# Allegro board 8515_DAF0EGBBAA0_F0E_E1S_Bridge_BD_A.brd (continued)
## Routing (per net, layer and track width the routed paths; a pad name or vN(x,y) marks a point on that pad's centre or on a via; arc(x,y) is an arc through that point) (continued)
P3V3_E1S_2: length 47.7
  TOP w0.305: v3(114.3,48.13) 114.3,48.51 114.81,49.02 R746.1
  TOP w0.508: R245.2 89.03,36.8 R246.2 88.4,37.85 v3(88.39,37.85)
  IN1 w0.508: 75.82,37.27 75.82,37.28 75.82,37.98 76.61,38.76 84.53,38.76 85.08,38.21 85.82,38.21 85.83,38.2 88.04,38.2 v3(88.39,37.85)
  VCC w0.508: v3(114.3,48.13) 114.1,48.13 113.62,47.66 113.07,47.66 111.52,46.1 111.51,46.1 110.32,44.91 107.17,44.91 105.55,43.29 94.35,43.29 90.93,39.88 89.52,39.88 88.39,38.75 v3(88.39,37.85)
  vias: v3(69.11,24.94) v3(69.77,24.99) v3(70,24.1) v3(70.64,24.08) v3(75.82,34.21)
P3V3_E1S_2_CB: length 1.7
  TOP w0.109: v3(65.34,19.6) 65.46,19.71 U28.B1
  BOTTOM w0.109: v3(65.34,19.6) 64.96,19.76 R459.1
P3V3_E1S_2_DVDT: length 2.2
  TOP w0.109: C67.1 v3(63.56,27.18) 63.61,27.13 64.93,27.13 U10.1
P3V3_E1S_2_GATE: length 3.3
  TOP w0.109: v3(64.44,22.83) 64.44,22.72 64.55,22.62 U28.A6
  BOTTOM w0.109: C121.1 v1(65.03,21.96) 64.55,21.96 64.44,22.07 v3(64.44,22.83)
P3V3_E1S_2_ILM: length 4.3
  TOP w0.109: v2(70.87,27.69) 70.3,27.69 70,27.38 R198.1 68.57,26.74 U10.7
P3V3_E1S_2_ISENSE: length 3.4
  TOP w0.109: U28.A1 64.12,20.12 v3(63.9,19.89)
  BOTTOM w0.109: v3(63.9,19.89) 63.4,20.39 v1(63.22,20.39) 63.22,19.78 R500.1
P3V3_E1S_2_OV: length 7.9
  TOP w0.203: U28.D3 67.52,21.12 68.24,20.4 v3(68.24,19.8)
  BOTTOM w0.254: R498.2 v1(68.88,22.65) 69.19,22.65 69.44,22.39 69.44,21.22 69.19,20.97 68.62,20.97 68.31,20.66 R499.1 68.24,20.35 v3(68.24,19.8)
P3V3_E1S_2_REG: length 1.4
  TOP w0.109: v3(66.96,19.69) 66.54,20.12 U28.D1
  BOTTOM w0.109: v3(66.96,19.69) 67,19.73 C130.2
P3V3_E1S_2_SCALED: length 10.1
  TOP w0.254: R746.2 R749.1 C284.2 115.84,46.79 117.27,45.36 117.53,45.36 117.79,45.11 v2(117.79,44.45) 118.82,43.41 119.53,43.41 120.53,42.41 121.28,42.1 U35.D1
P3V3_E1S_3: length 59.7
  TOP w0.381: R747.1 117.88,52.11 117.28,52.7 116.77,52.7 116.05,51.98 v3(116.05,51.13) ; R260.2 R261.2
  TOP w0.508: v3(110.74,36.3) 111.08,35.96 R260.2
  VCC w0.508: v3(97.94,33.3) 99.19,34.54 100.01,34.54 101.35,35.88 101.35,37.19 102.74,38.58 v3(102.92,38.58) 103.4,38.1 104.14,38.1 105.66,36.58 110.46,36.58 v3(110.74,36.3) ; v3(96.11,44.35) 96.47,44.7 97.69,44.7 98.32,44.07 105.18,44.07 106.84,45.73 108.75,45.73 109.88,46.86 111.2,46.86 112.83,48.49 113.23,48.49 114.71,49.96 114.88,49.96 v3(116.05,51.13)
  BOTTOM w0.508: v3(102.92,38.58) 102.69,38.81 100.69,38.81 98.67,36.79 98.03,36.79 95.83,38.99 95.83,42.52 96.11,42.8 v3(96.11,44.35)
  vias: v2(100.77,35.5)
P3V3_E1S_3_CB: length 2.5
  TOP w0.109: U29.B1 92.46,25.68 v3(92.35,25.58) 92.3,25.58 92.05,25.32 92,25.32 91.17,24.49 R461.1
P3V3_E1S_3_DVDT: length 3.1
  TOP w0.109: U9.1 92.4,34.38 91.97,34.8 v2(91.57,34.8) 90.57,34.8 C66.1
P3V3_E1S_3_GATE: length 3.1
  TOP w0.109: U29.A6 91.55,28.76 91.44,28.87 v3(91.44,28.98)
  BOTTOM w0.109: v3(91.44,28.98) 90.96,28.98 90.87,29.07 v1(90.87,29.57) 91.77,29.57 C124.1
P3V3_E1S_3_ILM: length 3.3
  TOP w0.109: U9.7 95.1,33.14 95.39,33.43 R197.1 96.6,33.64 v2(97.14,34.17)
P3V3_E1S_3_ISENSE: length 3.3
  TOP w0.109: U29.A1 91.57,25.87 v3(91.57,25.63) 91.52,25.58 90.45,25.58 90.19,25.32 R503.1
P3V3_E1S_3_OV: length 6.8
  TOP w0.203: 94.18,26.92 93.84,27.26 U29.D3
  TOP w0.254: 94.18,26.92 94.79,26.92 95.83,25.89 R502.1 96.69,25.89 96.99,25.59 v3(96.99,25.27) 96.99,24.09 96.67,23.77 96.11,23.77 R501.2
P3V3_E1S_3_REG: length 2.3
  TOP w0.109: C131.2 93.75,25.22 v3(94.11,25.58) 93.7,25.98 93.7,26.02 U29.D1
P3V3_E1S_3_SCALED: length 13.3
  TOP w0.127: U35.D2 121.82,42.5 121.18,42.5 120.81,42.87
  TOP w0.254: R747.2 R750.1 C285.2 117.07,50.02 116.46,49.4 116.46,46.89 117.48,45.87 117.86,45.87 119.01,44.71 v3(119.01,44.42) 119.48,43.95 119.73,43.95 120.81,42.87
P3V3_EDGE: length 50.4
  TOP w0.305: R462.1 133.32,17.91 v3(133.78,17.45)
  TOP w0.381: v3(119.28,20.85) R307.2 ; GF1.B11 25.85,3.43 ; 88.88,3.91 GF2.B11
  TOP w0.457: R23.1 v3(16.81,13.61) ; R24.1 v3(19.56,13.61)
  TOP w0.508: 25.85,3.43 25.85,8.69 v3(25.15,9.4)
  IN1 w0.508: v3(123.81,15.64) 123.96,15.49 130.42,15.49 131.39,15.9 131.61,16.12 131.61,16.94 132.12,17.45 v3(133.78,17.45)
  IN2 w0.508: v3(25.15,9.4) 24.46,10.08 24.46,14.35 22.1,16.71 16.56,16.71 16.05,16.2 16.05,14.58 16.81,13.82 v3(16.81,13.61)
  BOTTOM w0.508: R22.1 25.55,11.23 v3(25.22,11.56) ; v3(25.78,9.78) 25.4,9.4 v3(25.15,9.4) 23.77,10.78 R21.1 ; v3(19.56,13.61) 19.56,13.38 17.83,11.65 R7.1 16.81,12.11 v3(16.81,13.61)
  vias: v2(102.9,11.46) v2(105.18,14.4) v2(123.47,16.33) v3(28.37,12.12) v3(28.96,11.68) v3(56.52,13.21) v3(56.82,13.77) v3(57.15,13.13) v3(105.08,16.38) v3(105.09,15.72) v3(105.89,16.36) v3(105.89,15.7) v3(121.92,15.85) v3(122.61,16.46) v3(122.61,15.82) v3(124.47,16.28) v3(126.09,18.66)
P3V3_EDGE_CB: length 3.2
  TOP w0.254: R463.1 131,15.88 v3(130.59,16.29) 130.31,16.57 130.31,16.95 129.98,17.28 U30.B1
P3V3_EDGE_E1S_EN: length 3.9
  TOP w0.254: R308.1 120.24,15.64 120.68,16.08 U18.2
  TOP w0.508: v2(119.79,13.92) 120.28,14.41 ; 120.28,14.41 R305.2 ; 120.28,14.41 120.23,14.46 120.23,14.55 120.21,14.56 120.21,15.17 R308.1
P3V3_EDGE_GATE: length 2
  TOP w0.254: v3(126.83,16.25) 127.19,16.61 U30.A6
  BOTTOM w0.254: v3(126.83,16.25) 127.13,16.55 C127.1
P3V3_EDGE_ISENSE: length 3.6
  TOP w0.109: U30.A1 129.69,16.14 v3(130.9,14.94) 130.98,14.86 R475.1
P3V3_EDGE_OCP_DVDT: length 1.3
  TOP w0.109: C87.2 v3(119.55,16.57) 120.14,16.57 U18.1
P3V3_EDGE_OCP_FLT_N: length 11.4
  TOP w0.109: R309.1 121.77,20.86 120.8,20.86 R307.1 120.8,19.84 v5(121,19.64) 121.18,19.45 U18.6 ; v3(126.16,17.91) 126.29,17.78 U30.C7
  BOTTOM w0.109: v5(121,19.64) 122.39,18.24 122.39,17.3 122.71,16.98 124.35,16.98 125.27,17.91 v3(126.16,17.91)
P3V3_EDGE_OCP_ILM: length 2.1
  TOP w0.254: R306.1 v3(119.7,18.96) 119.82,19.08 120.43,19.08 120.68,18.82 U18.7
P3V3_EDGE_OV: length 8
  TOP w0.254: U30.D3 128.69,18.85 129.58,19.74 129.58,20.79 v2(129.79,21) 130.06,20.73 130.06,19.86 130.25,19.66 v3(131.33,19.66) 131.84,19.66 R474.1 132.11,19.78 132.91,18.98 R473.2
P3V3_EDGE_REG: length 3.2
  TOP w0.305: U30.D1 130.69,18.28 v3(130.96,18) 131.35,17.62 131.35,17.24 131.7,16.89 C132.2
P3V3_EDGE_UV: length 4.6
  TOP w0.109: U30.D2 129.19,18.63 129.51,18.94 v3(129.99,18.94) 130.38,18.94 130.62,19.18 131.85,19.18 R473.1 R462.2
P12V_AUX: length 7.6
  TOP w0.254: R450.1 88.87,56.11 v3(88.47,56.52) ; R173.1 37.87,57.08 v3(37.47,57.48) ; v3(13.21,57.48) 13.21,57.79 13.26,57.84 R439.1 ; v3(62.99,56.36) 63.39,55.96 R178.1
  TOP w0.305: v3(120.47,48.66) 120.27,48.66 R765.1
  TOP w0.508: R524.1 14.99,35.97 R525.1 14.98,35.26 14.55,34.83
  BOTTOM w0.356: R296.1 145.61,18.07 145.64,18.05 v3(145.64,17.98)
  BOTTOM w0.381: v3(145.11,29.77) 145.56,29.32 R297.1
  vias: v1(12.95,52.88) v1(19.89,45.75) v1(20.07,39.88) v1(38.14,53.26) v3(6.76,34.6) v3(6.77,33.79) v3(6.77,33.03) v3(6.77,32.27) v3(7.52,34.6) v3(7.53,33.79) v3(7.53,33.03) v3(7.53,32.27) v3(11.63,34.87) v3(11.63,34.11) v3(11.63,33.35) v3(12.4,34.87) v3(12.4,34.11) v3(12.4,33.35) v3(13.56,33.18) v3(13.56,32.54) v3(13.56,31.91) v3(13.56,31.27) v3(13.56,30.61) v3(13.57,29.95) v3(14.32,33.18) v3(14.32,32.54) v3(14.32,31.91) v3(14.32,31.27) v3(14.32,30.61) v3(14.33,29.95) v3(20.02,62.27) v3(20.46,61.32) v3(20.84,62.3) v3(21.3,61.33) v3(21.42,61.97) v3(28.42,48.82) v3(32.49,48.79) v3(33.15,48.79) v3(33.78,48.79) v3(34.42,48.79) v3(44.87,62.27) v3(45.5,61.29) v3(46.13,62.27) v3(46.8,61.43) v3(47.05,60.19) v3(58.22,48.64) v3(58.88,48.64) v3(59.51,48.64) v3(70.44,62.08) v3(71.06,61.1) v3(71.54,62.07) v3(72.28,61.43) v3(72.56,60.67) v3(84.15,48.82) v3(95.77,62.28) v3(96.45,61.24) v3(97.08,62.29) v3(97.7,61.66) v3(98.02,60.6)
P12V_AUX_0_ISENSE: length 1.3
  TOP w0.109: v3(11.88,28.71) 11.83,28.66 U33.A1
  BOTTOM w0.109: R511.1 12.44,28.99 12.16,28.71 v3(11.88,28.71)
P12V_AUX_CB: length 1.5
  TOP w0.109: v3(11.9,29.34) 11.72,29.16 U33.B1
  BOTTOM w0.109: R510.1 11.71,29.34 v3(11.9,29.34)
P12V_AUX_EN_MP5022: length 35.8
  TOP w0.109: R531.2 6.37,25.02 v3(6.58,25.02) ; U34.1 18.69,29.96 18.87,29.79 21.21,29.79 21.49,30.07 v3(21.89,30.07) 20.78,28.96 R522.2 21.6,27.64 R523.2
  IN2 w0.124: v3(21.89,30.07) 21.89,31.93 20.36,33.45 19.04,33.45 17.99,34.49 15.37,34.49 14.11,35.75 13.02,36.2 11.29,36.2 10.93,36.06 9.79,34.91 9.79,31.3 9.34,30.86 9.34,28.9 7.83,27.38 7.83,25.58 7.27,25.02 v3(6.58,25.02)
P12V_AUX_FB_MP5022: length 7.9
  TOP w0.109: R525.2 15.5,36.76 15.7,36.55 17.58,36.55 17.81,36.78 v3(18.27,36.78) 18.7,36.78 R526.2 17.57,35.25 17.26,35.25 16.79,34.77 16.41,34.77 16.3,34.66 U34.11
P12V_AUX_GATE: length 2
  TOP w0.109: U33.A6 8.83,27.71 v3(8.64,27.52) 8.69,27.47 C171.1
P12V_AUX_HSC_PWRGD: length 24
  TOP w0.109: v3(7.66,30.11) 8.28,30.11 U33.D7 ; U34.10 17.3,34.65 17.41,34.76 17.85,34.76 v3(18.71,35.62)
  IN1 w0.124: v3(7.66,30.11) 7.66,30.46 10.16,32.96 10.16,35.31 11.13,36.27 18.06,36.27 v3(18.71,35.62)
  BOTTOM w0.109: v3(7.66,30.11) v1(6.9,30.11) 6.14,29.35 6.14,28.23 5.66,27.75 R514.1 5.66,26.52 R513.2
P12V_AUX_IMON_MP5022: length 3.5
  TOP w0.109: U34.8 18.55,33.46 18.98,33.9 18.98,34.23 v3(19.32,34.56) R520.1 C178.2
P12V_AUX_ISET_MP5022: length 1.9
  TOP w0.109: U34.5 19.93,31.96 R521.1
P12V_AUX_OV: length 5.7
  TOP w0.109: U33.D3 v3(10.33,30.69)
  BOTTOM w0.109: R508.2 9.28,30.42 9.55,30.68 10.33,30.68 v3(10.33,30.69) 9.73,31.3 v1(8.3,31.3) 8.31,31.29 R509.1
P12V_AUX_PD_MP5022: length 2.7
  TOP w0.254: R524.2 16.75,35.74 16.49,35.49 16.49,35.49 15.98,35.27 v3(15.7,35) 15.4,34.69 U34.12
P12V_AUX_REG: length 3.8
  TOP w0.109: U33.D1 11.47,30.16 11.61,30.3 v3(11.61,30.66)
  BOTTOM w0.109: v3(11.61,30.66) 11.61,30.93 11.27,31.27 10.54,31.27 10.43,31.38 v1(10.43,31.73) C170.2
P12V_AUX_SS_MP5022: length 2.2
  TOP w0.109: U34.6 18.94,32.46 v3(19.08,32.61) 19.76,32.61 20.04,32.88 C177.1
P12V_AUX_TIMER_MP5022: length 2
  TOP w0.109: U34.4 19.32,31.46 v3(19.42,31.36) 19.78,31.36 C179.2
P12V_AUX_UV: length 13.8
  TOP w0.109: v3(10.97,30.67) 10.97,30.42 10.83,30.29 U33.D2 ; v3(6.48,24) 2.92,24 R530.2
  BOTTOM w0.109: v3(6.48,24) v1(8,25.53) 8,28 9.2,29.21 R508.1 10.08,30.01 R507.2 10.56,30.01 10.97,30.42 v3(10.97,30.67)
P12V_BIC_SCALED: length 6.4
  TOP w0.127: 120.59,44.63 120.59,44.33 121.22,43.7 U35.B1
  TOP w0.254: R765.2 R768.1 C291.2 119.11,46.4 120.38,45.12 120.59,44.63
P12V_E1S_0: length 9.1
  TOP w0.254: C73.1 17.13,50.44 16.92,50.65 16.91,50.65 16.77,50.8 U11.11
  TOP w0.381: C73.1 17.53,50.92 v3(17.43,51.02)
  IN1 w0.508: v3(17.43,51.02) 17.17,51.28 17.17,53.92 18.39,55.14 v3(20.62,55.14)
  vias: v2(19.25,54.35) v3(20.62,55.78)
P12V_E1S_0_CB: length 3.9
  TOP w0.254: R438.1 14.09,60.91 v3(15.03,59.97) 16,58.99 16,58.8 16.59,58.21 U22.B1
P12V_E1S_0_DVDT: length 1.9
  TOP w0.109: U3.1 24.04,59.69 24.03,59.7 v3(24.03,59.73)
  BOTTOM w0.109: C48.1 23.93,60.2 24.03,60.09 v3(24.03,59.73)
P12V_E1S_0_GATE: length 3.3
  TOP w0.254: v3(19.35,59.41) 19.21,59.27 U22.A6
  BOTTOM w0.109: C109.1 21.12,59.74 19.69,59.74 v3(19.35,59.41)
P12V_E1S_0_ILM: length 2.2
  TOP w0.109: v3(24,56.39) 23.54,56.85 U3.7
  BOTTOM w0.109: R169.2 v3(24,56.39)
P12V_E1S_0_IN_N: length 6.3
  TOP w0.109: v2(18.75,50.52) 17.79,51.48 17.12,51.48 16.93,51.3 U11.12
  TOP w0.254: R227.2 18.45,52.04 17.7,52.04 C74.2 17.41,52.04 16.64,52.04 16.21,51.61 U11.12
P12V_E1S_0_IN_P: length 3.7
  TOP w0.254: U11.13 15.88,52.02 16.41,52.55 17.41,52.55 C74.1 17.7,52.55 18.52,52.55 18.7,52.73 R226.2
P12V_E1S_0_IN_SENN: length 4.7
  TOP w0.254: R220.1B 23.1,52.72 22.84,52.98 21.77,52.98 20.79,52 19.82,52 R227.1
P12V_E1S_0_IN_SENP: length 4.7
  TOP w0.254: R220.2B 23.1,53.74 22.84,53.49 21.54,53.49 20.58,52.52 20.24,52.52 20.03,52.73 R226.1
P12V_E1S_0_ISENSE: length 4.7
  TOP w0.109: R464.1 14.04,61.61 15.08,60.57 15.72,60.57 v3(16.32,59.97) 16.71,59.58 U22.A1
P12V_E1S_0_L: length 120.9
  TOP w0.381: R752.1 v3(116.46,36.05)
  VCC w0.508: v3(36.6,36.58) 36.76,36.58 37.47,37.29 38.63,37.77 47.93,37.77 49.48,36.22 53.21,36.22 53.72,35.71 53.72,29.08 54.64,28.17 56.79,28.17 60.22,24.74 60.22,23.72 61.87,22.07 75.72,22.07 76.56,22.91 82.6,22.91 87.99,28.3 93.01,28.3 93.93,29.21 99.95,29.21 105.64,23.52 109.07,23.52 113.16,27.61 113.16,34.29 114.6,35.73 115.36,36.05 v3(116.46,36.05)
  BOTTOM w0.508: v3(24.89,41.53) 24.89,40.12 25.4,39.62 29.55,39.62 31.41,37.75 35.41,37.75 36.57,36.58 v3(36.6,36.58)
  vias: v2(21.84,45.21) v2(23.55,42.93)
P12V_E1S_0_OV: length 5.9
  TOP w0.254: U22.D3 17.71,56.7 16.97,55.96 v3(15.53,55.96) 15.18,55.96 R441.1 14.29,58.08 R440.2
P12V_E1S_0_REG: length 4.6
  TOP w0.305: U22.D1 16.64,57.14 15.8,57.14 15.37,57.57 v3(15.37,58.14) 15.37,58.8 14.27,59.89 C96.2
P12V_E1S_0_SCALED: length 5.2
  TOP w0.254: R752.2 R754.1 C287.2 119.25,37.72 119.51,37.97 121.29,37.97 U35.J1
P12V_E1S_1: length 7.9
  TOP w0.254: U12.11 43.17,49.04 43.52,48.69 C76.1
  TOP w0.508: v3(44.28,48.69) C76.1
  IN1 w0.508: v3(44.81,54.31) 44.28,53.78 v3(44.28,48.69)
  vias: v2(43.9,53.92) v3(44.81,54.94)
P12V_E1S_1_CB: length 3.6
  TOP w0.254: U23.B1 41.1,57.7 v3(39.93,58.87) 38.91,59.89 R444.1
P12V_E1S_1_DVDT: length 2.2
  TOP w0.109: v3(49.03,59.25) 48.81,59.02 U4.1
  BOTTOM w0.109: C49.1 48.92,59.77 49.03,59.65 v3(49.03,59.25)
P12V_E1S_1_GATE: length 2.5
  TOP w0.254: U23.A6 43.98,58.46 44.26,58.74 v3(44.26,59.14)
  BOTTOM w0.254: C110.1 43.59,58.48 v3(44.26,59.14)
P12V_E1S_1_ILM: length 2.2
  TOP w0.109: v3(48.67,55.7) 48.31,56.06 U4.7
  BOTTOM w0.109: R172.2 49.02,55.35 v3(48.67,55.7)
P12V_E1S_1_IN_N: length 7.2
  TOP w0.109: U12.12 43.28,49.54 43.38,49.45 44.24,49.45 44.92,48.77 v2(44.92,47.34)
  TOP w0.254: R242.2 44.43,50.01 43.81,50.01 C77.2 43.52,50.01 42.6,50.01 42.34,49.76 U12.12
P12V_E1S_1_IN_P: length 7.5
  TOP w0.109: U12.13 41.62,50.92 41.79,51.09 43.57,51.09 44.48,51.99 v2(44.63,51.99)
  TOP w0.254: U12.13 42.11,50.27 42.37,50.52 43.52,50.52 C77.1 43.81,50.52 44.41,50.52 R241.2
P12V_E1S_1_IN_SENN: length 4.7
  TOP w0.254: R235.1B 47.78,52.1 47.52,52.35 46.61,52.35 46,51.74 46,50.27 R242.1
P12V_E1S_1_IN_SENP: length 4.7
  TOP w0.254: R235.2B 47.78,53.11 47.52,52.86 46.38,52.86 45.49,51.96 R241.1
P12V_E1S_1_ISENSE: length 4.6
  TOP w0.109: R465.1 38.8,60.63 39.5,59.93 40.82,59.93 v3(41.01,59.74) 41.09,59.66 41.09,58.59 U23.A1
P12V_E1S_1_L: length 90.6
  IN1 w0.508: v3(61.72,29.84) 61.85,29.97 61.85,36.8 61.29,37.36 60.61,37.36 58.22,39.76 56,39.76 55.12,40.64 52.58,40.64 v3(51.44,41.78)
  VCC w0.508: v3(115.14,38.73) 115.14,38.28 114.63,37.77 114.12,37.77 112.37,36.02 112.37,28.25 111.4,27.28 108.74,27.28 108.08,27.94 105.79,27.94 104.44,26.58 103.72,26.58 99.44,30.86 89.47,30.86 86.23,27.62 83.13,27.62 82.68,28.07 80.14,28.07 79.5,27.43 67.77,27.43 66.8,26.46 63.27,26.46 62.76,26.97 62.76,29.16 62.2,29.72 61.85,29.72 v3(61.72,29.84)
  BOTTOM w0.381: R755.1 115.14,38.2 v3(115.14,38.73)
  vias: v2(46.96,48.97) v2(50.01,43.87)
P12V_E1S_1_OV: length 5.8
  TOP w0.254: U23.D3 42.48,56.17 41.43,55.12 40.01,55.12 v3(39.67,55.45) 39.06,56.06 R445.1 39.06,57.06 R443.2
P12V_E1S_1_REG: length 4.8
  TOP w0.305: U23.D1 41.48,56.56 41.17,56.25 40.44,56.25 40.13,56.56 v3(40.13,57.61) 40.13,57.82 39.07,58.88 C102.2
P12V_E1S_1_SCALED: length 10.3
  TOP w0.254: U35.K3 v4(122.62,36.9)
  IN1 w0.254: v4(122.62,36.9) 122.61,36.9 121.64,37.87 120.55,37.87 120.27,37.59 v3(116.43,37.59)
  BOTTOM w0.254: C288.2 R756.1 R755.2 116.19,38.1 116.43,37.86 v3(116.43,37.59)
P12V_E1S_2: length 2.1
  TOP w0.254: C79.1 69.26,31.77 U13.11
  TOP w0.381: C79.1 69.63,31.72 v3(69.93,31.41)
  vias: v3(67.12,53.94) v3(68.06,53.92) v3(69.65,54.91) v3(69.55,34.69) v3(69.68,54.26) v3(69.7,53.59) v3(70.19,34.8) v3(70.85,34.76) v3(71.44,35.06) v3(71.88,53.47)
P12V_E1S_2_CB: length 3.3
  TOP w0.254: U24.B1 66.71,57.35 v3(65.77,58.29) 65.29,58.78 R448.1
P12V_E1S_2_DVDT: length 2.3
  TOP w0.109: v3(74.53,59.04) 74.33,58.84 U5.1
  BOTTOM w0.109: C54.1 74.6,60.28 74.6,59.11 v3(74.53,59.04)
P12V_E1S_2_GATE: length 3
  TOP w0.254: U24.A6 69.5,58.11 69.64,58.25 v3(69.64,58.78)
  BOTTOM w0.109: v3(69.64,58.78) 69.64,57.67 C111.1
P12V_E1S_2_ILM: length 2.1
  TOP w0.109: R177.2 74.45,55.58 v3(74.47,55.58) 73.83,56.22 U5.7
P12V_E1S_2_IN_N: length 6.1
  TOP w0.109: v2(70.69,31.62) 70.04,32.27 U13.12
  TOP w0.254: R257.2 70.05,33.33 69.4,33.33 C80.2 69.15,33.32 68.72,33.32 68,32.59 U13.12
P12V_E1S_2_IN_P: length 5.6
  TOP w0.109: v2(66.19,34.37) 66.66,34.17 67.27,33.56 U13.13
  TOP w0.254: U13.13 67.67,33 68.5,33.83 69.09,33.83 C80.1 69.43,33.84 69.99,33.84 R256.2
P12V_E1S_2_IN_SENN: length 2.7
  TOP w0.254: R250.1B 72.9,33.72 72.63,33.99 71.98,33.99 R257.1
P12V_E1S_2_IN_SENP: length 2.8
  TOP w0.254: R256.1 71.4,34.14 71.76,34.49 72.64,34.49 72.9,34.75 R250.2B
P12V_E1S_2_ISENSE: length 4.4
  TOP w0.109: U24.A1 66.85,58 66.85,59.54 66.6,59.79 v3(64.94,59.79) R466.1
P12V_E1S_2_L: length 54.4
  TOP w0.381: v3(116.71,43.18) 116.46,42.93 R759.1
  IN1 w0.508: v3(74.01,34.05) 74.83,34.86 74.83,38.26 76.09,39.52 79.53,39.52 81.15,41.15 82.68,41.15 84,39.83 88.23,39.83 90.11,41.71 95.22,41.71 v3(96.52,40.41)
  VCC w0.508: v3(96.52,40.41) 97.69,40.41 98.25,40.97 104.08,40.97 104.65,40.4 110.32,40.4 111.33,39.4 114.05,39.4 116.28,41.63 116.28,42.75 v3(116.71,43.18)
  IN2 w0.508: v3(77.47,42.67) 76.72,42.67 76.67,42.72 v3(76.58,42.72)
  vias: v3(71.47,32.49) v3(71.47,31.86) v3(72.05,31.55) v3(76.99,43.31) v3(77.72,43.31)
P12V_E1S_2_OV: length 5.7
  TOP w0.254: R449.1 64.59,55.94 R447.2 64.71,55.96 v3(65.58,55.09) 66.29,55.09 66.4,54.99 67.2,54.99 68,55.79 U24.D3
P12V_E1S_2_REG: length 3.8
  TOP w0.305: C105.2 65.2,57.76 65.58,57.38 v3(65.58,56.85) 65.58,56.62 65.92,56.28 66.93,56.28 U24.D1
P12V_E1S_2_SCALED: length 12.8
  TOP w0.254: U35.K4 v4(123.42,36.9) ; R759.2 116.53,41.54 R760.1 116.53,40.06 v3(116.48,40.01) C290.2 116.48,39.22 115.99,38.74 v3(115.8,38.74)
  IN1 w0.178: v4(123.42,36.9) 123.01,37.3 123.01,37.9 122.81,38.1 122.17,38.1 121.89,38.38
  IN1 w0.254: v3(115.8,38.74) 116.4,38.14 120.08,38.14 120.32,38.38 121.89,38.38
P12V_E1S_3: length 6.6
  TOP w0.254: C82.1 96.81,39.54 96.55,39.8 96.31,39.9 U14.11
  TOP w0.508: v3(97.62,39.54) C82.1
  BOTTOM w0.508: v3(97.32,43.95) 97.32,39.84 v3(97.62,39.54)
  vias: v3(93.9,54.08) v3(96.44,55.06) v3(96.45,54.39)
P12V_E1S_3_CB: length 3.6
  TOP w0.254: U25.B1 92.19,57.5 91.4,58.29 v3(91.4,58.93) R452.1
P12V_E1S_3_DVDT: length 2
  TOP w0.109: U6.1 99.81,58.78 v3(100.03,59.3)
  BOTTOM w0.109: v3(100.03,59.3) C55.1
P12V_E1S_3_GATE: length 2.4
  TOP w0.254: U25.A6 94.98,58.26 95.19,58.47 v3(95.19,58.85)
  BOTTOM w0.254: v3(95.19,58.85) 95.19,58.59 94.57,57.97 C112.1
P12V_E1S_3_ILM: length 1.2
  TOP w0.109: R180.2 99.31,55.4 99.31,55.4 v3(99.31,55.97) U6.7
P12V_E1S_3_IN_N: length 2.8
  TOP w0.254: R272.2 97.82,40.93 C83.2 96.95,40.95 95.86,40.95 95.68,40.77 U14.12
P12V_E1S_3_IN_P: length 5.7
  TOP w0.109: v2(94.89,43.1) 94.41,42.62 94.41,42.06 94.96,41.52 U14.13
  TOP w0.254: R271.2 97.01,41.76 C83.1 96.95,41.7 96.47,41.7 96.42,41.76 95.94,41.76 95.3,41.12 U14.13
P12V_E1S_3_IN_SENN: length 4.1
  TOP w0.254: R265.1B 100.61,43.46 100.36,43.21 100.36,42.27 98.88,40.79 R272.1
P12V_E1S_3_IN_SENP: length 3
  TOP w0.254: R265.2B 99.59,43.46 99.85,43.21 99.85,42.52 99.09,41.76 R271.1
P12V_E1S_3_ISENSE: length 4.4
  TOP w0.109: R467.1 v3(90.46,59.94) 92.08,59.94 92.33,59.69 92.33,58.15 U25.A1
P12V_E1S_3_L: length 17
  TOP w0.381: v3(114.43,38.55) 114.88,38.1 R757.1
  VCC w0.508: v3(114.43,38.55) 111.72,38.55 111.16,38 105.38,38 103.23,40.16 v3(99.34,40.16)
  vias: v2(101.42,41.43)
P12V_E1S_3_OV: length 5.7
  TOP w0.254: R453.1 90.06,56.1 R451.2 90.19,56.11 v3(91.06,55.24) 91.77,55.24 91.88,55.14 92.68,55.14 93.48,55.94 U25.D3
P12V_E1S_3_REG: length 3.8
  TOP w0.305: C108.2 v3(90.39,57.91) 90.68,57.91 91.06,57.53 91.06,56.77 91.4,56.43 92.41,56.43 U25.D1
P12V_E1S_3_SCALED: length 9.2
  TOP w0.254: U35.K2 v4(121.82,36.9) ; 115.84,36.19 R758.1 R757.2 ; 115.84,36.19 v3(116.46,36.8) ; 115.84,36.19 C289.2
  IN1 w0.254: v3(116.46,36.8) 116.74,37.08 120.52,37.08 120.8,37.36 121.35,37.36 v4(121.82,36.9)
P12V_EDGE: length 172
  TOP w0.381: v3(118.49,49.4) 118.26,49.4 R766.1 ; GF2.B4 84.68,3.46 ; GF2.B6 85.88,3.73 ; 20.57,3.81 20.23,3.81 19.85,3.43 GF1.B1 ; GF1.B5 22.25,3.65 ; GF1.B3 21.05,3.53 ; GF2.B3 84.08,3.48 ; 83.29,3.66 82.88,3.25 GF2.B1 ; GF1.B6 22.85,3.56 ; GF1.B4 21.65,3.62 ; 20.45,3.42 GF1.B2 ; GF2.B2 83.48,3.54 ; GF2.B5 85.28,3.49
  IN1 w0.381: v3(122.65,58.17) 121.67,58.17 120.34,56.84 119.66,56.56 119.19,56.08 118.65,54.8 118.65,52.37 117.35,51.07 117.35,50.04 117.98,49.4 v3(118.49,49.4)
  IN2 w0.305: v3(86.36,7.11) 97.41,7.11 99.09,8.8 131.59,8.8 134.21,11.42 134.21,13.17 135.74,16.85 135.74,19.08 136.08,19.42 136.68,19.42 137.02,19.08 138.15,19.08 138.48,19.22 139.1,19.84 140.15,19.84 142.97,22.65 142.97,27.34 143.62,27.99 144.54,27.99 145.68,29.13 145.68,32.59 144.28,33.99 144.28,38.3 143.98,38.6 141.69,38.6 139.2,41.09 139.2,41.82 138.73,42.3 138.73,45.7 139.57,46.55 139.57,52.82 143.04,56.29 143.04,61.98 142.55,62.46 140.68,62.46 140.07,61.85 122.86,61.85 121.79,60.78 121.79,59.03 v3(122.65,58.17)
  BOTTOM w0.508: R507.1 10.47,28.99 v3(10.47,27.89)
  vias: v1(9.75,25.08) v1(10.93,22.38) v3(9.71,27.89) v3(9.71,27.13) v3(9.71,26.37) v3(10.47,27.13) v3(10.47,26.37) v3(16.46,28.15) v3(16.46,27.51) v3(16.58,20.16) v3(16.58,19.52) v3(17.1,28.15) v3(17.1,27.51) v3(17.22,20.16) v3(17.22,19.52) v3(17.66,15.21) v3(17.86,20.16) v3(17.86,19.52) v3(18.3,15.21) v3(18.49,20.16) v3(18.49,19.52) v3(18.93,15.21) v3(19.57,15.21) v3(20.32,7.11) v3(20.32,6.22) v3(20.32,5.33) v3(20.32,4.45) v3(21.72,7.11) v3(21.72,6.22) v3(21.72,5.33) v3(21.72,4.45) v3(23.24,7.24) v3(23.24,6.35) v3(23.24,5.46) v3(23.24,4.57) v3(83.31,6.99) v3(83.31,6.1) v3(83.34,5.21) v3(83.34,4.32) v3(84.84,6.99) v3(84.84,6.1) v3(84.84,5.21) v3(84.84,4.32) v3(86.23,6.22) v3(86.23,5.33) v3(86.31,4.27) v6(16.44,33.11) v6(16.44,32.21) v6(16.44,31.31) v6(16.44,30.41) v6(17.16,33.11) v6(17.16,32.21) v6(17.16,31.31) v6(17.16,30.41)
P12V_EDGE_BIC_SCALED: length 8.1
  TOP w0.127: U35.C1 121.42,43.03 120.44,44
  TOP w0.254: 120.44,44 118.03,46.41 117.67,46.41 117.07,47.01 C292.2 R769.1 R766.2
P12V_EDGE_R: length 2.9
  TOP w0.254: U33.A2 10.83,28.55 v3(11.21,28.18)
  BOTTOM w0.508: v3(11.21,28.18) 11.28,28.11 11.28,27.66 C180.1 11.68,27.21 11.68,26.12 R538.2
PVCC_1V2_PLL: length 4.7
  TOP w0.254: U35.G3 v4(122.62,39.3)
  BOTTOM w0.305: C228.1 122.11,39.6 121.52,39.6 C229.1 121.29,39.57 120.65,39.57 C230.1
  BOTTOM w0.381: L5.1 119.79,39.7 C230.1 ; C228.1 v4(122.62,39.3) U35.G3
  vias: v1(121.32,38.65)
PVCC_BIC_SPI: length 1.7
  TOP w0.109: U35.B8 v4(126.62,44.1)
  BOTTOM w0.254: v4(126.62,44.1) 126.98,44.47 C300.1
  BOTTOM w0.381: v4(126.62,44.1) 126.99,43.72 C232.1
  vias: v3(127.84,52.47) v3(128.56,52.47)
ADCVREFEXT0: length 0.6
  TOP w0.109: U35.F2 v4(121.82,40.1)
ADCVREFEXT1: length 0.6
  TOP w0.109: U35.G1 v4(121.02,40.1)
BIC_ADCAV33: length 2.8
  TOP w0.109: v4(124.22,36.9) U35.K5
  TOP w0.305: U35.J5 v4(124.22,37.7)
  BOTTOM w0.305: v4(124.22,37.7) C240.1 124.22,36.92 v4(124.22,36.9) C239.1
  vias: v1(118.98,36.62)
BIC_ADCVREFN0: length 3.4
  TOP w0.127: 119.76,41.53 120.5,41.53 121.05,41.3 U35.E1
  TOP w0.254: C204.1 118.75,42.04 118.75,42.04 119.23,42.04 C203.2 119.27,42.02 119.76,41.53
BIC_ADCVREFN1: length 5.6
  TOP w0.254: v4(122.61,38.5) 122.62,38.5 U35.H3
  BOTTOM w0.254: v4(122.61,38.5) 121.96,37.84 121.04,37.84 120.62,38.26 119.96,38.26 119.34,38.88 C206.2 119.23,38.86 C207.1
BIC_ADCVREFP0: length 4.6
  TOP w0.127: 120.17,42.03 120.97,41.7 v4(121.82,41.7) U35.E2
  TOP w0.254: C202.1 118.51,42.8 118.74,42.8 118.75,42.79 119.23,42.79 C203.1 119.39,42.82 120.17,42.03
BIC_ADCVREFP1: length 5.4
  TOP w0.254: U35.J3 v4(122.62,37.7)
  BOTTOM w0.254: C205.1 118.49,38.08 C206.1 119.69,37.65 v1(120.41,37.65) 120.57,37.49 122.11,37.49 122.29,37.67 122.59,37.67 v4(122.62,37.7)
BIC_ESPI_SELECT: length 11.7
  TOP w0.109: U35.D14 v4(132.22,42.5)
  BOTTOM w0.109: v4(132.22,42.5) 132.42,42.5 132.86,42.94 133.3,42.94 133.8,42.44 134.32,42.44 135.25,43.38 135.25,45.14 v1(135.64,45.52) R775.1 135.22,46.97 135.1,47.09 135.1,49.53 135.21,49.64 R779.2
BIC_EXTRST_N: length 220.1
  TOP w0.109: R4594.2 130.46,11.67 133.36,14.57 134.44,17.18 134.44,19.87 133.66,20.65 133.66,22.63 132.86,23.43 132.86,25.04 134.34,26.53 v3(134.34,27.48) ; v3(13.03,13.61) 13.03,13.1 R5.1 ; R619.2 v4(122.17,46.35) 121.74,45.92 121.74,45.57 122.62,44.69 122.62,44.1 U35.B3
  IN1 w0.124: v3(121.94,22.79) 121.36,23.37 118.26,23.37 118.19,23.44 115.62,23.44 114.96,22.78 114.96,21.64 113.28,19.96 112.19,19.96 111.67,20.48 110.5,20.48 109.98,21 104.99,21 99.1,26.88 90.21,26.88 85.2,21.88 74.1,21.88 71.01,18.79 63.54,18.79 61.11,21.22 52.67,21.22 49.63,24.26 44.63,24.26 41.78,21.41 37.16,21.41 36.09,20.35 25.68,20.35 23.01,17.68 23.01,13.97 20.17,11.13 16.87,11.13 15,12.99 13.65,12.99 v3(13.03,13.61)
  IN2 w0.124: v3(121.94,22.79) 122.76,23.6 125.33,23.6 127.84,26.11 127.84,26.97 128.57,27.71 134.12,27.71 v3(134.34,27.48) 134.52,27.48 136.17,29.13 136.17,42.94 135.13,43.98 135.13,46.99 136.14,48 136.14,49.71 134.18,51.67 134.18,53.05 133.31,53.92 132.52,53.92 132.11,54.33 132.11,55.12 131.24,55.99 130.56,55.99 129.5,57.04 128.69,57.04 128.4,57.34 126.69,57.34 126.2,56.84 126.2,56.52 124.95,55.27 124.95,54.63 124.36,54.04 124.36,53.34 124.44,53.26 124.44,52.51 124,52.06 122.17,52.06 121.5,51.4 121.5,50.58 121.82,50.26 121.82,48.77 121.7,48.65 121.7,46.82 v4(122.17,46.35)
BIC_EXTRST_N_IO_EXP: length 154.3
  TOP w0.109: R4603.1 v3(14.07,13.59) ; U43.2 119.82,11.56 119.08,10.82 R4599.2 118.28,10.07 118.17,9.96 115.5,9.96 114.96,10.18 v3(114.77,10.37)
  IN1 w0.124: v3(114.77,10.37) 114.11,10.37 113.23,11.25 111.52,11.25 109.77,9.51 107.98,9.51 107.69,9.21 105.33,9.21 105.06,9.48 99.69,9.48 98.82,8.61 98.79,8.61 98.78,8.6 53.8,8.6 52.9,9.5 38.82,9.5 33.46,14.86 28.07,14.86 27.59,14.38 26.52,14.38 21.23,9.09 15.34,9.09 14.99,8.74 13.38,8.74 9.15,12.97 9.15,14.08 9.61,14.55 12.24,14.55 12.69,14.1 13.56,14.1 v3(14.07,13.59)
  BOTTOM w0.109: R4592.2 134.34,18.32 134.34,16.61 133.55,15.82 133.55,15.81 133.44,15.7 v1(132.69,15.7) 128.36,15.7 127.71,15.05 121.59,15.05 121.08,14.53 121.08,12.53 118.26,9.71 115.43,9.71 v3(114.77,10.37)
BIC_EXTRST_N_IO_EXP_R: length 17.9
  TOP w0.109: U48.5 137.17,25.01 137.52,25.35 138.15,25.35 138.54,24.96 138.54,20.41 138.01,19.88 136.54,19.88 136.43,19.77 v5(136.43,18.84)
  BOTTOM w0.109: R4592.1 136.27,19 v5(136.43,18.84) 136.94,19.35 139.36,19.35 141.46,20.23 142,20.77 U44.2
BIC_EXTRST_N_R: length 9.5
  TOP w0.109: U43.4 121.8,10 121.92,9.88 128.26,9.88 v2(128.85,10.46) 128.85,11.05 128.65,11.25 R4594.1
BIC_FWSPICK: length 236.5
  TOP w0.109: v3(130.62,20.34) 131.08,20.8 132.86,20.8 v3(133.18,21.12) ; v3(144.16,54.98) R651.1 143.51,55.68 143.24,55.95 143.24,59.93 J29.1 ; U35.E7 v4(125.82,41.7) ; R793.1 v3(14.99,13.61)
  IN1 w0.124: v3(14.99,13.61) 17.04,11.56 20.06,11.56 22.61,14.1 22.61,17.84 25.55,20.78 35.74,20.78 37.92,22.96 42.69,22.96 44.42,24.69 49.74,24.69 52.83,21.6 61.41,21.6 63.6,19.4 64.1,19.4 64.84,20.14 65.71,20.14 66.08,20.51 72.18,20.51 73.92,22.26 85.05,22.26 90.1,27.32 94.58,27.32 95.32,28.05 98.53,28.05 105.11,21.46 110.09,21.46 110.59,20.97 112.38,20.97 v3(112.88,20.47) ; v3(132.25,30.88) 132.25,31.06 132.8,31.62 135.55,31.62 135.7,31.77 135.7,37.35 134.57,38.48 134.57,39.92 133.21,41.28 126.14,41.28 125.82,41.61 v4(125.82,41.7)
  IN2 w0.124: v4(125.82,41.7) 126.24,42.12 126.24,45.09 126.4,45.25 126.4,47.79 126.94,48.33 126.94,49.18 127.2,49.44 127.2,53.98 126.98,54.2 v3(126.85,54.2)
  BOTTOM w0.109: R797.2 134.69,21.12 v3(133.18,21.12) ; v3(126.85,54.2) 124.29,54.2 123.48,55.01 123.48,55.98 123.37,56.09 122.45,56.09 122.19,56.34 122.19,60.04 122.3,60.15 123.29,60.15 123.49,60.35 123.49,61.67 124.09,62.27 127.46,62.27 128.12,61.61 132.5,61.61 132.99,61.11 132.99,59.8 134.96,57.83 137.16,57.83 138.47,59.14 140.26,59.14 140.37,59.03 140.37,57.98 140.84,57.5 140.84,57.42 143.29,54.98 v3(144.16,54.98) ; v3(112.88,20.47) 113.05,20.47 115.47,18.05 118.38,18.05 118.56,17.87 119.76,17.87 120.36,18.47 120.36,19.69 121.34,20.67 122.02,20.67 122.62,20.07 125.96,20.07 126.5,19.53 129.09,19.53 129.57,20.01 130.28,20.01 v3(130.62,20.34) 131.52,21.25 131.52,23.18 131.81,23.47 131.81,26.1 131.91,26.2 131.91,26.58 131.77,26.72 131.77,28.37 131.91,28.51 131.91,28.89 131.77,29.03 131.77,29.33 132.25,29.81 v3(132.25,30.88)
BIC_FWSPICK_IO_EXP: length 12.1
  TOP w0.109: v3(137.74,24.71) 137.39,24.36 U48.6
  BOTTOM w0.109: U44.3 141.5,22.76 139.32,24.94 137.98,24.94 v3(137.74,24.71) 137.17,24.14 v1(137.17,22.89) 137.17,21.82 136.15,20.8 R797.1
BIC_FWSPICK_R: length 6.4
  TOP w0.109: v4(145.64,55.93) 145.43,56.14 144.34,56.14 144.16,56.32 R646.2
  BOTTOM w0.109: v4(145.64,55.93) 144.48,55.93 144.16,56.26 144.16,58.31 J29.2
BIC_FWSPICS1_N: length 15.1
  TOP w0.109: U35.F7 v4(125.82,40.9)
  IN1 w0.124: v3(126.36,49.02) 126.87,48.51 126.87,48.12 126.58,47.83 126.25,47.83 125.21,46.78 125.21,44.95 125.45,44.71 125.95,44.71 126.21,44.44 126.21,42.31 126.03,42.12 125.58,42.12 125.43,41.97 125.43,41.21 125.74,40.9 v4(125.82,40.9)
  BOTTOM w0.109: v3(126.36,49.02) 126.45,49.02 127.51,50.09 v1(127.51,50.59) 126.99,50.59 126.88,50.47 126.88,50.15 R627.2
BIC_FWSPIDQ2: length 12.9
  TOP w0.109: U35.D8 v4(126.62,42.5)
  BOTTOM w0.109: v4(126.62,42.5) 126.25,42.86 126.25,44.89 126.49,45.14 126.49,46.13 125.92,46.71 125.92,47.96 125.9,47.98 125.9,48 125.78,48.12 125.78,51.66 125.67,51.77 v1(125.38,51.77) 124.98,51.77 124.76,51.55 124.76,50.55 124.88,50.44 R628.2
BIC_FWSPIDQ3: length 11.2
  TOP w0.109: U35.D5 v4(124.22,42.5)
  BOTTOM w0.109: v4(124.22,42.5) 124.58,42.86 124.58,43.57 124.41,43.74 124.41,46.13 124.94,46.65 125.38,46.65 125.55,46.82 125.55,47.81 125.45,47.92 125.02,47.92 124.67,48.27 124.67,49.32 124.23,49.76 v1(123.93,49.76) 123.35,49.76 123.17,49.58 R629.2
BIC_FWSPIMISO: length 12.1
  TOP w0.109: U35.C8 127.42,43.3 127.42,45.47 127.56,45.82 127.56,46.04 127.46,46.27 126.9,46.84 126.9,51.94 R781.1 126.36,52.83 126.26,52.94 v3(125.71,52.94) 125.51,52.94 125.22,52.65 R784.2
BIC_MB_FWSPICK: length 12.1
  TOP w0.109: R793.2 14.99,12.06 v2(13.69,10.77) 10.92,8 10.92,4.16 10.06,3.3 GF1.OCP_B5
BIC_SECUREBOOT: length 8
  TOP w0.109: R777.2 135.78,49.64 136.14,49.28 136.14,47.48 R773.1 135.64,46.66 133.96,44.99 v3(133.75,44.99) 133.36,44.99 133.01,44.64 133.01,44.1 U35.B15
BIC_SP1_CS1: length 3.5
  TOP w0.109: U35.B6 125.01,44.1 125.01,46.76 R636.2
BIC_SRST_N: length 242
  TOP w0.109: R4593.2 119.28,12.93 119.61,12.6 120.35,12.6 121.26,11.68 121.26,9.86 121.61,9.51 128.86,9.51 133.67,14.31 134.78,17 134.8,17.03 134.8,20.02 134.02,20.8 134.02,25.69 134.81,26.47 134.81,28.1 134.7,28.21 v3(134.4,28.21) ; U35.C3 v4(122.62,43.3) ; R4587.2 128.6,61.59 128.22,61.21 128.22,56.58 v3(128.44,56.37) ; v3(11.43,13.59) 11.43,13.07 R792.1
  IN1 w0.124: v3(11.43,13.59) 12.59,12.43 14.97,12.43 16.69,10.72 20.45,10.72 23.42,13.69 23.42,17.37 25.98,19.94 40.87,19.94 44.73,23.8 49.56,23.8 52.52,20.84 60.95,20.84 63.38,18.41 71.29,18.41 74.38,21.5 85.36,21.5 89.26,25.41 90.6,25.41 91.7,26.51 98.95,26.51 104.83,20.62 109.82,20.62 110.34,20.1 111.52,20.1 112.03,19.59 113.44,19.59 115.37,21.51 115.37,22.58 115.75,22.96 117.93,22.96 118.53,22.36 121.13,22.36 v3(121.21,22.44)
  IN2 w0.124: v4(122.62,43.3) 122.71,43.39 122.71,51.43 122.94,51.66 124.14,51.66 124.85,52.37 125.32,53.52 125.32,55.11 126.58,56.37 126.58,56.69 126.85,56.96 127.84,56.96 v3(128.44,56.37) 130.04,54.76 131.25,54.76 131.64,54.37 131.64,54.09 132.64,53.09 132.64,52.63 135.1,50.16 135.1,47.95 134.72,47.57 134.72,40.76 134.94,40.55 134.94,37.36 135.6,36.7 135.6,29.13 134.68,28.21 v3(134.4,28.21) 134.07,28.21 133.97,28.11 128.41,28.11 127.44,27.14 127.44,26.28 125.25,24.08 122.4,24.08 121.21,22.89 v3(121.21,22.44)
  BOTTOM w0.109: v4(122.62,43.3) 122.3,43.61 122.3,44.48 121.53,45.24 R617.2
BIC_SRST_N_IO_EXP: length 167.6
  TOP w0.109: U42.1 114.77,13.43 113.73,14.46 R4598.2 113.73,15.27 v3(114.01,15.54) ; R4602.1 v3(12.24,13.61)
  IN1 w0.124: v3(114.01,15.54) 112.38,15.54 112.05,15.21 110.79,15.21 109.84,16.17 107.78,16.17 107.39,16.56 107.39,17.13 106.37,18.15 96.63,18.15 93.48,15 89.18,15 87.16,17.02 87.16,18.42 86.3,19.28 75.32,19.28 72.31,16.27 61.55,16.27 60.94,16.89 52.45,16.89 49.17,13.61 41.82,13.61 37.37,18.07 27.72,18.07 27.22,17.56 24.81,17.56 24.25,17.01 24.25,13.33 20.87,9.95 14.71,9.95 13.94,10.72 12.07,10.72 9.62,13.17 9.62,13.78 9.96,14.12 11.74,14.12 v3(12.24,13.61)
  BOTTOM w0.109: R4591.2 135.01,16.42 134.16,15.57 134.16,15.04 132.87,13.75 128.62,13.75 v1(128.27,14.1) 127.93,14.44 121.95,14.44 121.69,14.18 121.69,11 119.85,9.16 115.05,9.16 113.17,11.04 111.7,11.04 111.06,11.68 111.06,14.68 111.65,15.27 113.73,15.27 v3(114.01,15.54)
BIC_SRST_N_IO_EXP_R: length 21.7
  TOP w0.109: v3(136.4,18.07) 136.66,18.07 137.09,18.5 137.09,19.33 137.24,19.48 v4(138.12,19.48) 138.46,19.48 138.96,19.98 138.96,25.1 138.25,25.81 137.42,25.81 137.27,25.66 U48.4
  IN1 w0.124: v3(143.03,19.81) 138.33,19.81 136.58,18.07 v3(136.4,18.07)
  BOTTOM w0.109: U44.1 142.5,20.34 v3(143.03,19.81) ; R4591.1 135.86,18.04 136.38,18.04 v3(136.4,18.07)
BIC_SRST_N_R: length 1.4
  TOP w0.109: R4593.1 118.08,12.13 v3(117.74,11.79) 117.41,12.13 U42.4
BIC_USB2A_1V2: length 0.6
  TOP w0.109: U35.E5 v4(124.22,41.7)
  vias: v1(124.88,47.3)
BIC_USB2A_3V3: length 1.7
  TOP w0.127: U35.F5 v4(125.01,40.9)
  BOTTOM w0.381: C247.1 v4(125.01,40.9) C246.1
  vias: v4(125.02,43.3) v4(125.82,44.1)
BMC_HARTBEAT_LED: length 8.8
  TOP w0.109: R579.1 121.43,47.77 121.71,48.05 121.71,49.54 121.36,49.89 v3(121.21,49.89) 119.48,49.89 118.95,50.42 118.95,51.3 118.59,53.1 118.49,53.34 D24.C
BMC_HARTBEAT_LED_R: length 2.9
  TOP w0.109: R579.2 121.16,45.64 122.22,44.59 U35.A2
CARD_TYPE_R: length 12.6
  BOTTOM w0.109: R11.1 R10.1 ; R11.1 14.6,10.92 v1(15.88,10.92) 17.2,10.92 R7.2 ; R11.1 14.55,10.06 14.26,9.76 GF1.OCP_A12
CLK_25M_OSC_BIC_CLKIN: length 13.8
  TOP w0.109: U35.D4 v4(123.42,42.5) ; R660.2 v3(120.02,51.05)
  IN1 w0.124: v3(120.02,51.05) 119.68,50.72 119.68,42.75 120.32,42.11 123.03,42.11 v4(123.42,42.5)
CLK_25M_OSC_BIC_CLKOUT: length 2.3
  TOP w0.109: OSC1.3 120.12,53.96 120.02,53.85 120.02,53.15 v3(119.95,53.09) 120.02,53.02 R660.1
CLK_100M_E1S_0_DN: length 39.4
  TOP w0.132: v3(26.43,36.91) 26.78,36.57 27.29,36.57 27.42,36.69 J4.B14 ; v3(40.38,22.21) 40.04,22.54 40.04,25 40.12,25.08 U32.14
  BOTTOM w0.132: v3(40.38,22.21) 40.03,22.55 40.03,22.91 40.16,23.04 41.7,23.04 45.73,24.71 46.16,25.14 v4(46.16,28.13) 46.16,28.75 41.96,32.95 38.9,32.95 37.7,34.15 31.54,36.92 29.85,36.92 29.51,36.58 26.77,36.58 v3(26.43,36.91)
CLK_100M_E1S_0_DP: length 39.4
  TOP w0.132: U32.13 39.62,25.08 39.7,25 v4(39.7,23.83) 39.7,22.54 v3(39.36,22.21) ; v3(26.43,35.9) 26.75,36.22 27.29,36.22 27.42,36.09 J4.B15
  BOTTOM w0.132: v3(26.43,35.9) 26.77,36.24 29.65,36.24 29.99,36.58 31.47,36.58 32.5,36.11 32.61,35.84 32.97,35.68 33.24,35.78 33.6,35.62 33.7,35.35 34.06,35.19 34.33,35.29 34.69,35.13 34.79,34.86 35.15,34.7 35.43,34.8 37.51,33.87 38.76,32.61 41.82,32.61 45.82,28.61 45.82,25.28 45.53,25 41.64,23.38 40.02,23.38 39.69,23.05 39.69,22.53 v3(39.36,22.21)
CLK_100M_E1S_1_DN: length 17.6
  TOP w0.132: U32.18 42.15,26.69 42.23,26.61 43.91,26.61 45.11,27.81 45.75,31.44 v4(49.84,35.53) 50.87,36.57 52.79,36.57 52.92,36.7 J5.B14
CLK_100M_E1S_1_DP: length 17.6
  TOP w0.132: U32.17 42.15,26.19 42.23,26.27 44.05,26.27 45.42,27.65 46.07,31.28 v4(47.93,33.14) 51.01,36.22 52.79,36.22 52.92,36.1 J5.B15
CLK_100M_E1S_2_DN: length 51.4
  TOP w0.132: v3(44.57,33.08) 44.9,32.75 44.9,32.66 44.78,31.98 44.07,29.86 43.97,29.58 43.87,29.51 43.63,29.33 43.31,29.11 42.31,29.11 42.23,29.19 U32.23 ; v3(77.22,36.9) 77.55,36.57 78.29,36.57 78.42,36.7 J6.B14
  BOTTOM w0.132: v3(44.57,33.08) 44.91,33.42 44.91,34.34 45.45,34.88 v4(46.82,34.88) 47.08,34.88 48.78,36.59 53.12,36.59 53.6,37.06 58.47,37.06 66.7,28.83 71.2,28.83 71.57,29.2 71.57,29.88 74.72,33.03 74.72,34.91 76.37,36.57 76.88,36.57 v3(77.22,36.9)
CLK_100M_E1S_2_DP: length 51.4
  TOP w0.132: U32.22 42.23,28.69 42.31,28.77 43.41,28.77 44.26,29.36 v4(45.03,31.64) 45.11,31.89 45.24,32.63 45.24,32.63 45.27,32.76 v3(45.59,33.08) ; v3(77.22,35.89) 77.55,36.22 78.29,36.22 78.42,36.1 J6.B15
  BOTTOM w0.132: v3(77.22,35.89) 76.88,36.22 76.51,36.22 75.06,34.77 75.06,32.89 71.91,29.74 71.91,29.06 71.34,28.49 66.56,28.49 58.33,36.72 53.74,36.72 53.26,36.25 48.92,36.25 47.22,34.54 45.59,34.54 45.25,34.2 45.25,33.42 v3(45.59,33.08)
CLK_100M_E1S_3_DN: length 85.9
  TOP w0.132: v3(39.92,34.26) 40.26,33.92 40.26,33.28 40.37,32.63 40.37,32.09 40.25,31.8 39.88,31.43 39.71,31.01 39.71,30.82 39.62,30.73 U32.28 ; v3(102.62,36.9) 102.95,36.57 103.79,36.57 103.92,36.7 J7.B14
  BOTTOM w0.132: v3(102.62,36.9) 102.28,36.57 101.46,36.57 98.72,33.82 98.72,32.26 97.59,31.13 87.39,31.13 87.17,31.34 87.17,34.61 84.87,36.92 80.28,36.92 78.69,38.51 76.38,38.51 72.77,34.9 72.77,34.48 72.05,33.77 71.05,33.77 70.55,33.26 66.46,33.26 61.28,38.44 52.39,38.44 51.2,39.63 v4(44.12,39.63) 43.47,39.63 40.21,36.37 40.21,34.55 v3(39.92,34.26)
CLK_100M_E1S_3_DP: length 85.9
  TOP w0.132: J7.B15 103.92,36.1 103.79,36.22 102.95,36.22 v3(102.62,35.89) ; U32.27 40.12,30.75 40.05,30.82 40.05,30.94 40.17,31.24 40.54,31.61 40.71,32.03 40.71,32.63 40.71,32.63 40.6,33.31 40.6,33.92 v3(40.93,34.26)
  BOTTOM w0.132: v3(40.93,34.26) 40.9,34.26 40.55,34.61 40.55,36.23 41.75,37.43 42.04,37.43 42.32,37.71 42.32,38 42.6,38.28 42.89,38.28 43.17,38.56 43.17,38.85 43.61,39.29 v4(47.32,39.29) 51.06,39.29 52.25,38.1 61.14,38.1 66.31,32.92 70.69,32.92 71.19,33.43 72.2,33.43 73.11,34.34 73.11,34.76 76.52,38.17 78.54,38.17 80.14,36.58 84.72,36.58 86.83,34.47 86.83,31.2 87.25,30.79 97.73,30.79 99.06,32.12 99.06,33.68 100.76,35.38 101.05,35.38 101.33,35.66 101.33,35.95 101.6,36.22 102.28,36.22 v3(102.62,35.89)
CLK_100M_MB_DN: length 38.1
  TOP w0.132: v3(34.55,21.97) 34.21,22.31 34.21,22.91 34.42,23.12 34.42,23.51 34.21,23.72 34.21,25.17 34.49,25.45 34.79,25.45 35.07,25.73 35.07,26.02 35.35,26.3 35.64,26.3 35.92,26.58 35.92,26.87 36.32,27.27 36.46,27.27 36.54,27.19 U32.6 ; GF1.B14 27.65,3.16 27.78,3.29 27.78,6.74 29.57,9.28 29.76,10.38 v4(29.76,13.46) 29.76,13.62 v3(29.41,13.97)
  IN2 w0.155: v3(29.41,13.97) 29.74,14.3 29.74,14.68 31.2,15.71 31.25,15.99 31.63,16.25 31.91,16.2 32.29,16.47 32.34,16.75 32.72,17.01 33,16.96 33.37,17.23 33.42,17.51 33.8,17.77 34.08,17.72 34.46,17.99 34.51,18.27 34.89,18.53 35.17,18.48 35.55,18.75 35.6,19.03 35.97,19.29 36.25,19.24 36.63,19.51 36.68,19.79 37.06,20.05 37.34,20 37.77,20.3 37.77,21.42 36.71,22.16 36.43,22.11 36.05,22.38 36,22.66 35.52,23 35.33,23.03 34.95,23.06 34.57,23.08 34.22,22.8 34.22,22.3 v3(34.55,21.97)
CLK_100M_MB_DP: length 38.2
  TOP w0.132: U32.5 36.55,27.69 36.47,27.61 36.18,27.61 33.87,25.31 33.87,22.31 v3(33.54,21.97) ; GF1.B15 28.25,3.16 28.12,3.29 28.12,6.63 29.01,7.89 29.89,9.15 30.1,10.35 v4(30.1,10.79) 30.1,13.64 v3(30.43,13.97)
  IN2 w0.155: v3(33.54,21.97) 33.86,22.3 33.86,22.97 34.46,23.45 35.37,23.39 35.66,23.34 38.13,21.61 38.13,20.12 30.1,14.5 30.1,14.3 v3(30.43,13.97)
CLKBUF_ADR0_TRI: length 8.1
  TOP w0.109: U32.32 v3(36.38,30.39)
  BOTTOM w0.109: R478.2 37.34,27.71 R479.1 36.96,27.32 36.96,26.77 36.73,26.54 v1(36.32,26.54) 36.32,27.68 36.63,27.98 36.63,30.14 v3(36.38,30.39)
CLKBUF_E1S_0_OE_N: length 159.9
  TOP w0.109: U32.12 39.12,24.61 38.66,23.51 38.55,23.4 38.13,22.37 38.13,22.1 38.23,21.85 38.78,21.48 41.22,21.48 43.58,23.84 43.58,24.61 44.72,25.74 v3(45.1,25.74) ; R630.2 129.54,51.4 130.55,52.41 131.49,52.8 132.68,53.99 v3(132.68,54.47)
  IN2 w0.124: v3(132.68,54.47) 133.27,55.06 134.38,55.06 135.47,53.97 135.57,53.97 137.91,51.63 137.91,47.64 137.35,47.08 137.35,41.72 137.69,41.38 137.69,40.19 138.51,39.37 138.51,35.8 140.41,33.9 140.41,30.36 139.51,29.46 138.95,29.46 138.59,29.1 138.59,28.11 137.43,26.95 136.43,26.95 133.92,24.44 132.53,24.44 131.95,23.85 131.95,23.13 129.75,20.93 129.75,20.18 128.9,19.33 122.98,19.33 122.35,18.7 120.25,18.7 117.99,16.44 117.99,14.98 116.23,13.21 116.08,13.21 116.08,13.21 108.84,13.21 108.23,12.6 98.24,12.6 96.82,11.18 86.56,11.18 86.06,11.68 61.4,11.68 61.38,11.69 61.31,11.69 61.23,11.78 61.21,11.78 47.49,25.49 45.52,25.49 45.27,25.74 v3(45.1,25.74)
CLKBUF_E1S_0_OE_R_N: length 6.6
  TOP w0.109: U35.A10 128.62,45.07 129.19,45.65 129.19,46.62 R639.2 129.9,46.97 130.05,47.12 130.05,48.73 129.73,49.05 v3(129.32,49.05) 129.54,49.27 R630.1
CLKBUF_E1S_1_OE_N: length 149.9
  TOP w0.109: v3(42.77,27.11) 42.69,27.19 U32.19 ; R631.2 130.12,50.44 130.01,50.55 130.01,51.33 130.8,52.12 131.72,52.5 133.71,54.48 v3(133.98,54.48)
  IN2 w0.124: v3(42.77,27.11) 43.5,26.38 45.11,26.38 45.28,26.21 45.3,26.21 45.39,26.12 45.42,26.12 45.68,25.87 47.65,25.87 61.37,12.16 61.38,12.16 61.47,12.07 86.2,12.07 86.71,11.56 96.67,11.56 98.09,12.98 107.98,12.98 108.58,13.59 116.07,13.59 117.6,15.13 117.6,17.73 119.33,19.45 120.38,19.45 120.7,19.13 122.25,19.13 122.83,19.71 128.53,19.71 129.34,20.52 129.34,21.05 131.37,23.08 131.37,24.63 131.81,25.06 134,25.06 136.47,27.53 137.45,27.53 138.21,28.29 138.21,30.51 139.97,32.27 139.97,33.71 136.58,37.1 136.58,43.28 135.98,43.88 135.98,46.57 137.31,47.9 137.31,49.52 136.73,50.1 136.73,50.84 135.58,52 135.58,52.28 133.98,53.88 v3(133.98,54.48)
CLKBUF_E1S_1_OE_R_N: length 7.2
  TOP w0.109: U35.B10 129.02,44.1 129.02,44.95 130.56,46.48 R640.2 131.07,47.49 131.07,48.59 130.56,49.1 R631.1
CLKBUF_E1S_2_OE_N: length 168.9
  TOP w0.109: R632.2 127.51,50.93 127.63,51.05 128.06,51.05 130.32,53.31 v3(130.52,53.31) ; v3(107.67,13.54) 107.67,12.88 106.93,12.14 106.93,10.92 108.43,9.42 113.44,9.42 115.26,8.67 115.7,8.23 129.82,8.23 131.64,10.05 v3(131.64,10.15) ; v3(42.93,29.69) U32.24
  IN1 w0.124: v3(141.79,36.61) 141.7,36.7 141.7,37.71 141.58,37.83 138.79,37.83 138.26,38.35 136.65,38.35 135.72,39.29 135.72,43.05 134.74,44.03 134.74,50.5 133.52,51.72 133.16,51.72 132.16,52.71 130.65,52.71 130.52,52.83 v3(130.52,53.31)
  IN2 w0.124: v3(141.79,36.61) 142.35,36.06 142.35,35.18 143.13,34.4 143.13,30.55 142.88,30.3 142.88,29.11 142.12,28.35 142.12,26.67 141.78,26.33 141.78,24.18 140.64,23.04 139.45,23.04 138.32,21.91 138.32,20.33 137.91,19.93 137.49,19.93 136.95,20.46 135.14,20.46 134.63,19.95 134.63,16.86 133.02,12.97 133.02,12.32 131.64,10.93 v3(131.64,10.15) ; v3(107.67,13.54) 107.49,13.36 97.93,13.36 96.51,11.94 86.87,11.94 86.36,12.45 61.62,12.45 61.54,12.53 61.52,12.53 47.81,26.25 46.71,26.25 46.71,28.91 45.94,29.69 v3(42.93,29.69)
CLKBUF_E1S_2_OE_R_N: length 6
  TOP w0.109: U35.A9 127.82,45.42 127.92,45.68 127.92,46.56 R641.2 127.89,46.97 128.02,47.1 128.02,48.72 v3(127.74,49) 127.74,49.4 R632.1
CLKBUF_E1S_3_OE_N: length 174.7
  TOP w0.109: v3(39.3,31.22) 39.12,31.04 U32.29 ; v3(133.5,11.69) 133.5,10.52 130.19,7.21 115.6,7.21 114.87,7.93 113.3,8.59 107.97,8.59 105.79,10.76 105.79,11.99 106.91,13.11 v3(106.91,13.84) ; v3(131.23,53.2) 131.1,53.2 130.81,52.92 130.35,52.72 128.52,50.9 R724.2
  IN1 w0.124: v3(142.5,37.02) 142.5,37.65 141.89,38.26 138.89,38.26 138.42,38.73 136.98,38.73 136.17,39.54 136.17,43.21 135.13,44.25 135.13,50.64 133.47,52.3 133.11,52.3 132.21,53.2 131.23,53.2 v3(131.23,53.2)
  IN2 w0.124: v3(106.91,13.84) 97.88,13.84 96.35,12.31 87.03,12.31 86.43,12.91 61.68,12.91 47.97,26.63 47.11,26.63 47.11,29.25 45.89,30.48 40.05,30.48 v3(39.3,31.22) ; v3(142.5,37.02) 142.98,36.54 142.98,35.29 143.51,34.76 143.51,32.7 144.06,32.14 144.06,29.26 142.5,27.7 142.5,26.51 142.24,26.25 142.24,23.23 140.12,21.11 138.95,21.11 138.69,20.86 138.69,20.12 138.16,19.59 138.06,19.55 137.21,19.55 136.87,19.89 135.43,19.89 135.08,19.53 135.08,16.76 133.5,12.95 v3(133.5,11.69)
CLKBUF_E1S_3_OE_R_N: length 6.8
  TOP w0.109: U35.B9 128.22,44.1 128.22,45.44 128.29,45.6 128.29,46.73 R788.2 128.76,46.97 129.03,47.24 129.03,48.56 128.52,49.07 R724.1
DELTA_L_85_5INCH_BOT_DN: length 127
  BOTTOM w0.132: J11.1 -7.15,72.53 -7.15,67.48 -7.38,66.17 -8.03,65.72 -11.17,66.27 -11.78,65.84 -11.94,64.93 -11.52,64.32 -6.88,63.5 -6.54,63.02 -6.64,62.46 -7,62.21 -11.19,62.94 -11.78,62.53 -11.95,61.56 -11.55,61 -6.78,60.16 -6.54,59.8 -6.66,59.12 -7.01,58.88 -11.19,59.62 -11.78,59.21 -11.94,58.25 -11.54,57.66 -6.78,56.83 -6.54,56.47 -6.66,55.8 -7.01,55.55 -11.19,56.29 -11.78,55.88 -11.93,54.98 -11.47,54.32 -6.78,53.5 -6.54,53.14 -6.62,52.66 -6.65,52.51 -6.66,52.47 -7.01,52.22 -11.19,52.96 -11.78,52.55 -11.94,51.62 -11.51,51 -6.78,50.17 -6.54,49.81 -6.62,49.34 -6.62,49.34 -6.66,49.14 -7.01,48.89 -11.19,49.63 -11.78,49.22 -11.93,48.32 -11.48,47.67 -6.78,46.84 -6.54,46.48 -6.6,46.15 -6.62,46 -6.65,45.84 -6.66,45.81 -7.01,45.56 -11.19,46.3 -11.78,45.89 -11.95,44.92 -11.55,44.35 -6.78,43.51 -6.54,43.16 -6.66,42.48 -7.01,42.23 -11.19,42.97 -11.78,42.56 -11.94,41.6 -11.54,41.02 -6.79,40.18 -6.54,39.82 -6.65,39.2 -7.06,38.91 -11.24,39.65 -11.77,39.27 -11.95,38.26 -11.55,37.69 -8.27,37.11 -7.47,35.96 -7.35,35.78 -7.15,34.68 -7.15,31.48 J10.2
DELTA_L_85_5INCH_BOT_DP: length 127
  BOTTOM w0.132: J11.2 -6.81,72.53 -6.81,67.45 -7.07,65.97 -7.95,65.36 -11.09,65.91 -11.47,65.64 -11.58,65 -11.32,64.63 -6.82,63.84 -6.68,63.81 -6.18,63.1 -6.32,62.27 -6.92,61.85 -11.11,62.58 -11.46,62.34 -11.59,61.64 -11.35,61.31 -6.59,60.47 -6.18,59.88 -6.35,58.93 -6.93,58.52 -11.11,59.26 -11.47,59.01 -11.58,58.33 -11.34,57.98 -6.59,57.14 -6.18,56.55 -6.27,56.03 -6.35,55.6 -6.93,55.19 -11.11,55.93 -11.46,55.68 -11.57,55.06 -11.28,54.64 -6.59,53.81 -6.18,53.22 -6.31,52.46 -6.32,52.44 -6.34,52.27 -6.64,52.06 -6.93,51.86 -11.11,52.6 -11.46,52.35 -11.58,51.7 -11.31,51.31 -6.59,50.48 -6.18,49.89 -6.35,48.94 -6.93,48.53 -11.11,49.27 -11.46,49.02 -11.57,48.4 -11.28,47.98 -6.59,47.15 -6.18,46.56 -6.26,46.09 -6.31,45.81 -6.32,45.78 -6.33,45.72 -6.37,45.59 -6.93,45.2 -11.11,45.94 -11.46,45.69 -11.59,45 -11.35,44.66 -6.59,43.82 -6.18,43.23 -6.35,42.28 -6.93,41.87 -11.11,42.61 -11.46,42.36 -11.52,42.02 -11.58,41.68 -11.34,41.33 -6.59,40.49 -6.18,39.9 -6.34,39 -6.98,38.55 -11.16,39.29 -11.46,39.08 -11.59,38.34 -11.36,38 -8.07,37.42 -7.13,36.07 -7.02,35.91 -6.81,34.71 -6.81,31.48 J10.1
DELTA_L_85_5INCH_IN1_DN: length 127
  IN1 w0.155: v3(-11.69,72.17) -11.88,71.97 -11.88,67.88 -12.2,66.1 -13.22,65.38 -16.22,65.91 -16.53,65.69 -16.66,64.96 -16.45,64.65 -11.63,63.8 -11.2,63.18 -11.39,62.11 -11.82,61.81 -14.09,62.21 -14.2,62.22 -14.2,62.23 -16.28,62.59 -16.53,62.42 -16.66,61.66 -16.41,61.31 -11.66,60.47 -11.26,59.91 -11.44,58.9 -12.01,58.51 -16.25,59.26 -16.53,59.07 -16.66,58.33 -16.41,57.98 -11.64,57.14 -11.29,56.64 -11.48,55.55 -12.01,55.18 -16.19,55.92 -16.54,55.67 -16.65,55 -16.41,54.65 -11.66,53.82 -11.25,53.23 -11.42,52.26 -12.01,51.85 -16.19,52.59 -16.54,52.34 -16.66,51.67 -16.41,51.33 -11.66,50.49 -11.27,49.93 -11.45,48.91 -12.01,48.52 -16.19,49.26 -16.54,49.01 -16.66,48.34 -16.41,48 -11.66,47.16 -11.28,46.61 -11.46,45.58 -12.01,45.19 -16.19,45.93 -16.54,45.68 -16.66,45.01 -16.41,44.67 -11.66,43.83 -11.3,43.31 -11.49,42.22 -12.01,41.86 -16.19,42.6 -16.54,42.36 -16.66,41.68 -16.41,41.34 -11.95,40.55 -11.95,40.55 -11.66,40.5 -11.28,39.95 -11.46,38.92 -12.01,38.53 -16.19,39.27 -16.54,39.03 -16.66,38.36 -16.41,38.01 -13.14,37.43 -12.09,35.91 -11.88,34.71 -11.88,32.04 v3(-11.69,31.85)
  BOTTOM w0.132: J13.1 v3(-11.69,31.85) ; J14.2 v3(-11.69,72.17)
DELTA_L_85_5INCH_IN1_DP: length 127
  IN1 w0.155: v3(-12.44,31.85) -12.24,32.04 -12.24,34.68 -12.43,35.78 -13.35,37.1 -16.62,37.68 -17.03,38.27 -16.86,39.24 -16.27,39.65 -12.09,38.91 -11.79,39.12 -11.66,39.87 -11.87,40.17 -12.01,40.2 -12.02,40.2 -16.62,41.01 -17.03,41.6 -16.86,42.56 -16.27,42.98 -12.09,42.24 -11.82,42.43 -11.68,43.23 -11.87,43.5 -16.62,44.34 -17.03,44.93 -16.86,45.89 -16.27,46.31 -12.09,45.57 -11.78,45.79 -11.65,46.52 -11.87,46.83 -16.62,47.67 -17.03,48.26 -16.86,49.22 -16.27,49.64 -12.09,48.9 -11.77,49.12 -11.65,49.84 -11.87,50.16 -16.62,51 -17.03,51.59 -16.86,52.55 -16.27,52.97 -12.09,52.23 -11.75,52.47 -11.63,53.14 -11.87,53.49 -16.62,54.33 -17.03,54.92 -16.86,55.88 -16.27,56.3 -12.09,55.56 -11.81,55.75 -11.67,56.55 -11.85,56.81 -16.62,57.66 -17.03,58.25 -16.85,59.27 -16.34,59.64 -12.09,58.89 -11.77,59.11 -11.64,59.82 -11.87,60.15 -16.62,60.99 -17.04,61.58 -16.85,62.63 -16.36,62.97 -14.03,62.56 -13.74,62.51 -13.74,62.51 -11.91,62.18 -11.71,62.32 -11.58,63.1 -11.84,63.47 -16.65,64.32 -17.04,64.88 -16.86,65.9 -16.3,66.29 -13.31,65.76 -12.52,66.31 -12.24,67.91 -12.24,71.97 v3(-12.44,72.17)
  BOTTOM w0.132: J13.2 v3(-12.44,31.85) ; J14.1 v3(-12.44,72.17)
DELTA_L_85_5INCH_IN2_DN: length 127
  TOP w0.132: J18.2 v3(-9.15,31.85) ; J17.1 v3(-9.15,72.17)
  IN2 w0.155: v3(-9.15,31.85) -9.34,32.04 -9.34,34.71 -9.55,35.91 -10.6,37.43 -13.87,38.01 -14.12,38.36 -14,39.03 -13.65,39.27 -9.47,38.53 -8.84,38.97 -8.68,39.87 -9.12,40.5 -13.87,41.34 -14.12,41.68 -14,42.36 -13.65,42.6 -9.47,41.86 -8.88,42.27 -8.71,43.22 -9.13,43.83 -13.87,44.67 -14.12,45.01 -14,45.68 -13.65,45.93 -9.47,45.19 -8.88,45.6 -8.72,46.5 -9.19,47.17 -13.87,48 -14.12,48.34 -14,49.01 -13.65,49.26 -9.48,48.52 -8.87,48.95 -8.71,49.9 -9.12,50.49 -13.87,51.33 -14.12,51.67 -14,52.34 -13.65,52.59 -9.47,51.85 -8.88,52.26 -8.72,53.17 -9.18,53.83 -13.87,54.65 -14.12,55 -14,55.67 -13.65,55.92 -9.47,55.18 -8.88,55.59 -8.71,56.55 -9.13,57.15 -13.87,57.98 -14.12,58.33 -14,59 -13.65,59.25 -9.52,58.52 -8.87,58.97 -8.73,59.76 -9.25,60.5 -13.87,61.31 -14.11,61.66 -14.01,62.26 -13.58,62.56 -9.39,61.82 -8.75,62.27 -8.6,63.09 -9.11,63.8 -13.88,64.64 -14.12,64.98 -14.08,65.19 -14.05,65.34 -13.99,65.69 -13.68,65.91 -10.5,65.36 -9.53,66.04 -9.34,67.12 -9.34,71.97 v3(-9.15,72.17)
DELTA_L_85_5INCH_IN2_DP: length 127
  TOP w0.132: J18.1 v3(-9.9,31.85) ; J17.2 v3(-9.9,72.17)
  IN2 w0.155: v3(-9.9,72.17) -9.7,71.97 -9.7,67.15 -9.86,66.24 -10.59,65.74 -13.76,66.29 -14.32,65.9 -14.34,65.75 -14.36,65.67 -14.43,65.25 -14.49,64.9 -14.09,64.32 -9.31,63.48 -8.98,63 -9.07,62.48 -9.47,62.2 -13.66,62.94 -14.34,62.47 -14.49,61.58 -14.08,60.99 -9.46,60.17 -9.11,59.67 -9.2,59.18 -9.6,58.9 -13.73,59.62 -14.32,59.21 -14.49,58.25 -14.08,57.66 -9.34,56.82 -9.09,56.46 -9.2,55.8 -9.55,55.56 -13.59,56.27 -13.73,56.3 -14.32,55.88 -14.49,54.92 -14.08,54.33 -9.39,53.5 -9.1,53.08 -9.2,52.47 -9.55,52.23 -13.73,52.97 -14.32,52.55 -14.49,51.59 -14.08,51 -9.33,50.16 -9.09,49.81 -9.2,49.16 -9.57,48.9 -13.73,49.64 -14.32,49.22 -14.49,48.26 -14.08,47.67 -9.4,46.84 -9.1,46.41 -9.2,45.81 -9.55,45.57 -13.73,46.31 -14.32,45.89 -14.49,44.93 -14.08,44.34 -9.34,43.5 -9.09,43.14 -9.2,42.48 -9.55,42.24 -13.73,42.98 -14.32,42.56 -14.49,41.6 -14.08,41.01 -9.33,40.17 -9.06,39.79 -9.17,39.18 -9.55,38.91 -13.73,39.65 -14.32,39.24 -14.49,38.27 -14.08,37.68 -10.81,37.1 -9.89,35.78 -9.7,34.68 -9.7,32.04 v3(-9.9,31.85)
